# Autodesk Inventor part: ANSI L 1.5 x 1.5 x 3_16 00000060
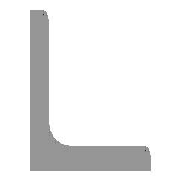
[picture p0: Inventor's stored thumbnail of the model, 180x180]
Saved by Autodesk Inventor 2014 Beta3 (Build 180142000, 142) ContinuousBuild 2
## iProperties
_CCFamilyMember: 5
_CCFamilyDisplayName: ANSI L (Equal angles) - Angle Steel
_FrameMemberDoc: Frame Member File
_Version: 15.0.0
_GetPNFromCC: 1
Created: 2010-11
Part Number: ANSI L 1.5 x 1.5 x 3_16 00000060
Material: Steel, Mild
Description: Angle Steel
Document SubType Name: Modeling
Standard: ANSI
Designer: Beta-8540w
Standards Organization: ANSI
Language: en-US
Size Designation: L 1.5 x 1.5 x 3/16
Categories: <MemberInstance><Categories><Category DisplayName="Structural Shapes" InternalName="089c4875-fa83-4c05-b084-43b9cc11f5ed" Mnemonic="GRDR"><CategoryParameter Dis
Stock Number: L 1.5 x 1.5 x 3/16
Density: 7.86 g/cm^3
Appearance: Steel
IsCustomPart: 1
G_L: 31.773 in
G_W: 1.500 in
G_H: 1.500 in
+3B2E30B5-4963-484D-8D95-D946A704ABD9+CUTDETAIL1: Cut
Author: Beta-8540w
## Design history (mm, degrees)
node "Start plane"
node "End plane"
sketch "Sketch"
  geometry: L1 (38.1, 0)-(0, 0); L2 (0, 0)-(0, 38.1); L3 (0, 38.1)-(2.476, 38.1); L4 (4.762, 35.814)-(4.762, 9.589); L5 (9.588, 4.763)-(35.814, 4.763); L6 (38.1, 2.477)-(38.1, 0); L7 (0, -11.041)-(0, 31.538); L8 (-11.041, 0)-(31.538, 0); L9 (0, 48.496)-(0, -20.964) reference; L10 (-20.964, 0)-(48.496, 0) reference; A1 r 4.826 centre (9.588, 9.589) between (4.762, 9.589) and (9.588, 4.763); A2 r 2.286 centre (2.476, 35.814) between (4.762, 35.814) and (2.476, 38.1); A3 r 2.286 centre (35.814, 2.477) between (38.1, 2.477) and (35.814, 4.763); 3 further points
  constraints: 16 end point, 6 point on circle, 6 point on line, 6 tangent, 4 parallel, 3 centre point, 2 collinear, 1 equal radius, 1 horizontal, 1 perpendicular
  dimensions: "d0" = 38.1 distance between parallel lines of L6 L2 (= G_H); "d1" = 38.1 distance between parallel lines of L3 L1 (= G_H); "d2" = 4.7625 distance between parallel lines of L2 L4 (= G_T); "d3" = 4.7625 distance between parallel lines of L1 L5 (= G_T); "d10" = 0 distance between parallel lines of L7 L2 (computed from ex); "d11" = 0 distance between parallel lines of L8 L1 (computed from d10); "d14" = 4.826 radius of A1 (= G_IR); "d15" = 2.286 radius of A2 (= G_ER)
extrude "Body" new body sketch "Sketch" stored distance "d4" = 807.0404 (= G_L); taper "d5" = 0 deg
node "Driven Length"
  sketch "Sketch3"
    geometry: L1 (0, 0)-(10, 0) reference
    constraints: 2 end point, 1 horizontal
  workplane "Work Plane3"
  sketch "Sketch4"
    geometry: L1 (-2, 0)-(12, 0) reference; L2 (-2, 807.04)-(12, 807.04) reference
    dimensions: "d17" = 807.0404 distance between parallel lines of L1 L2 (derived)
workplane "Work Plane4"
split "Split1"
body "Solid1"
other parameters: "G_H" = 38.1 [user parameter; used in 2 equation terms], "G_T" = 4.7625 [user parameter; used in 2 equation terms], "G_ER" = 2.286 [user parameter; used in 1 equation term], "G_IR" = 4.826 [user parameter; used in 1 equation term], "G_L" = 807.0404 (= d17) [user parameter; used in 1 equation term], "ex" = 0 [user parameter; used in 1 equation term], "G_OFFSET_START" = 0 [user parameter; used in 1 equation term], "G_OFFSET_END" = -29.72503 [user parameter; used in 1 equation term], "d12" = 0 (computed from G_OFFSET_START), "d13" = 807.0404 (= G_OFFSET_END + B_L), "B_L" = 836.76542 [user parameter; used in 1 equation term], "d16" = 90 deg, "MAS" = 0.26787 [user parameter]
